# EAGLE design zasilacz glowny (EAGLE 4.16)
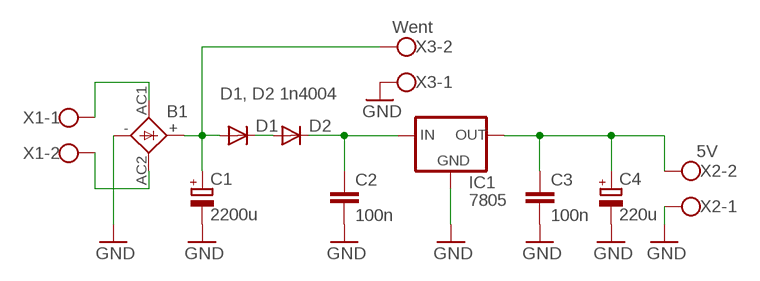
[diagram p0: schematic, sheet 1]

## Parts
B1  FB15A  [FB15A]
C1  2200u  CPOL-EUE7.5-16  [E7,5-16]
C2  100n  C5/2.5  [C5B2.5]
C3  100n  C5/2.5  [C5B2.5]
C4  220u  CPOL-EUE3.5-8  [E3,5-8]
D1  1N4004  [DO41-10]
D2  1N4004  [DO41-10]
IC1  7805  78XXS  [78XXS]
X1  W237-102  [W237-102]
X2  5V  W237-102  [W237-102]
X3  Went  W237-102  [W237-102]

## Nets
GND: B1.- C1.- C2.2 C3.2 C4.- IC1.GND X2.1 X3.1
N$1: B1.AC1 X1.1
N$2: B1.AC2 X1.2
N$3: C2.1 D2.C IC1.IN
N$4: B1.+ C1.+ D1.A X3.2
N$5: C3.1 C4.+ IC1.OUT X2.2
N$6: D1.C D2.A

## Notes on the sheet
- D1, D2 1n4004

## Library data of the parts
B1 = rectifier:FB15A: FAGOR RECTIFIER grid 3 x 5 mm
C1 C4 = rcl:CPOL-EU: POLARIZED CAPACITOR, European symbol
C2 C3 = capacitor-wima:C: CAPACITOR
D1 D2 = diode:1N4004: DIODE
IC1 = v-reg:78XXS: VOLTAGE REGULATOR
X1-X3 = con-wago-500:W237-102: WAGO SCREW CLAMP

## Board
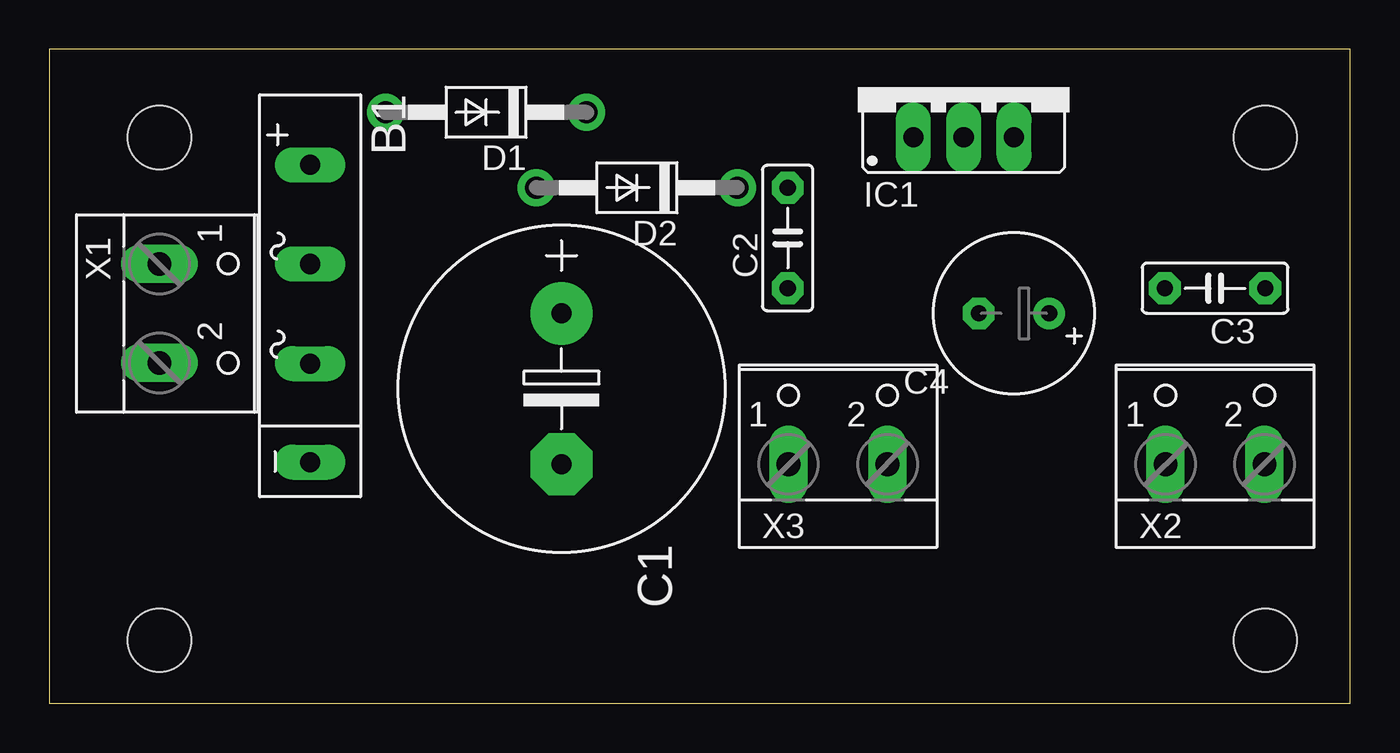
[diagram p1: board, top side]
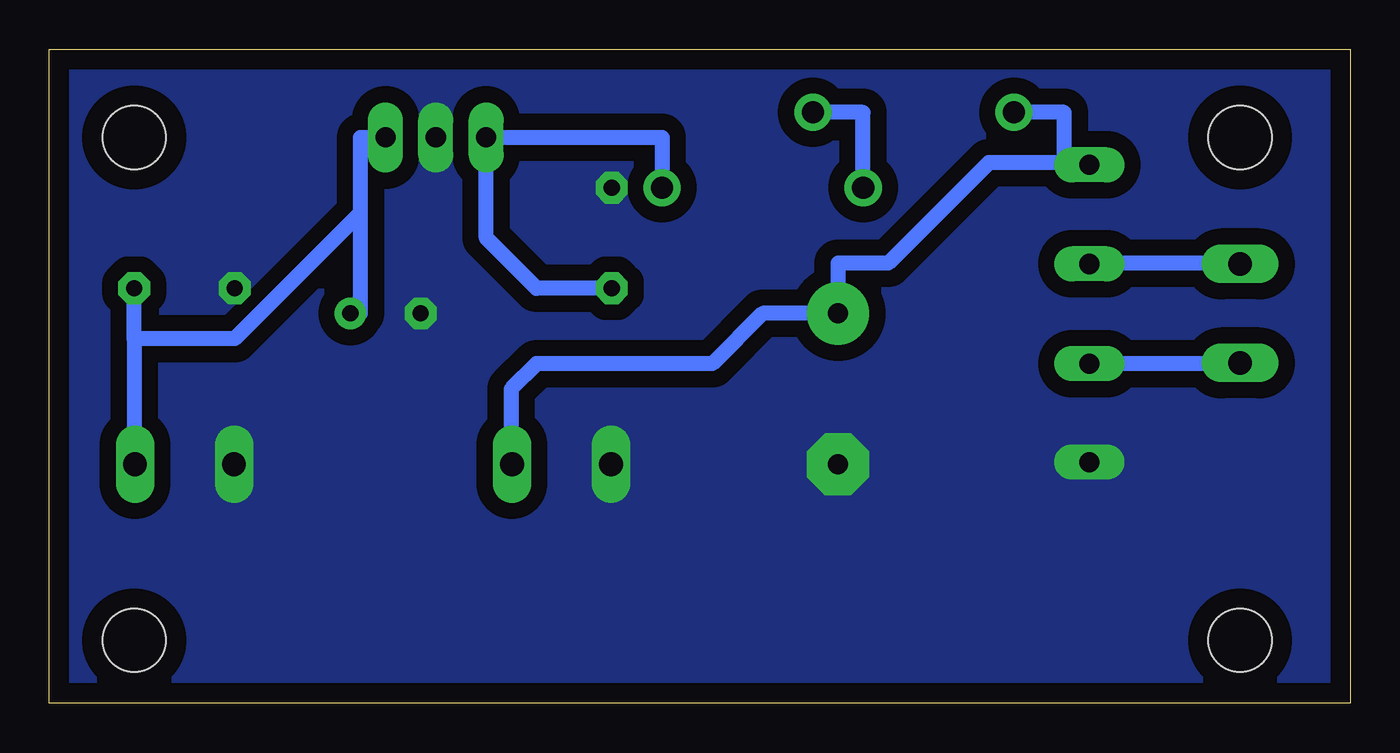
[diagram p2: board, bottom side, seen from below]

Size 65.71 x 33.01 mm. Coordinates in mm from the lower left corner, seen from the top.
Outline: 0,0 65.71,0 65.71,33.01 0,33.01 0,0
Copper layers (1*16): Top 0.035mm / dielectric 1.5mm / Bottom 0.035mm
Design rules "default": minimum track width 30mil, minimum drill 24mil, track to track 8mil, track to pad 8mil, pad to pad 8mil, via to via 8mil, smd to smd 8mil, copper to edge 40mil, drill to drill 8mil, minimum pad ring 15mil, minimum via ring 8mil, stop-mask expansion 4mil, vias tented up to drill 0mil, thermal gap 10mil
Holes 3.2 mm at 5.55,28.57 5.55,3.17 61.43,28.57 61.43,3.17

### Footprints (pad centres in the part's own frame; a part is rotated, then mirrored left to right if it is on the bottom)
FB15A = drill 1.016 long: + -7.5,0; - 7.511,0; AC1 -2.496,0; AC2 2.533,0
E7,5-16 = drill 1.016 pad 3.15 round: + -3.81,0 | drill 1.016 pad 3.15 octagon: - 3.81,0
C5B2.5 = drill 0.813 pad 1.6 octagon: 1 -2.54,0; 2 2.54,0
E3,5-8 = drill 0.813 pad 1.6 round: + -1.778,0 | drill 0.813 pad 1.6 octagon: - 1.778,0
DO41-10 = drill 1.118 round: A 5.08,0; C -5.08,0
78XXS = drill 1.016 long: GND 0,-2.54; IN -2.54,-2.54; OUT 2.54,-2.54
W237-102 = drill 1.194 long: 1 -2.5,-1.27; 2 2.5,-1.27

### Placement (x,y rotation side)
B1  13.17,19.68 270 top
C1  25.87,15.87 270 top
C2  37.3,23.49 90 top
C3  58.89,20.95 180 top
C4  48.73,19.68 180 top
D1  22.06,29.84 180 top
D2  29.68,26.03 180 top
IC1  46.19,31.11 0 top
X1  6.82,19.68 270 top
X2  58.89,13.33 0 top
X3  39.84,13.33 0 top

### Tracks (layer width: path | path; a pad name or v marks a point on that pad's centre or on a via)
GND
  pour Bottom (isolate 0.813, no thermals): 0.47,32.38 0.47,0.63 65.24,0.63 65.24,32.38
N$1
  Bottom 0.762: B1.AC1 11.9,22.22 6.82,22.22 X1.1
N$2
  Bottom 0.762: B1.AC2 11.9,17.14 6.82,17.14 X1.2
N$3
  Bottom 0.762: C2.1 41.11,20.95 43.65,23.49 IC1.IN 34.76,28.57 D2.C
N$4
  Bottom 0.762: 14.44,27.3 14.44,29.84 D1.A | X3.2 42.38,13.33 42.38,15.87 41.11,17.14 32.22,17.14 29.68,19.68 C1.+ 25.87,22.22 23.33,22.22 18.25,27.3 14.44,27.3 | B1.+ 14.44,27.3
N$5
  Bottom 0.762: 61.43,18.41 61.43,13.33 X2.2 | 61.43,18.41 C3.1 | 50,24.76 50,28.57 IC1.OUT | 50,24.76 50,19.68 C4.+ | 61.43,18.41 56.35,18.41 50,24.76
N$6
  Bottom 0.762: D2.A 24.6,29.84 D1.C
